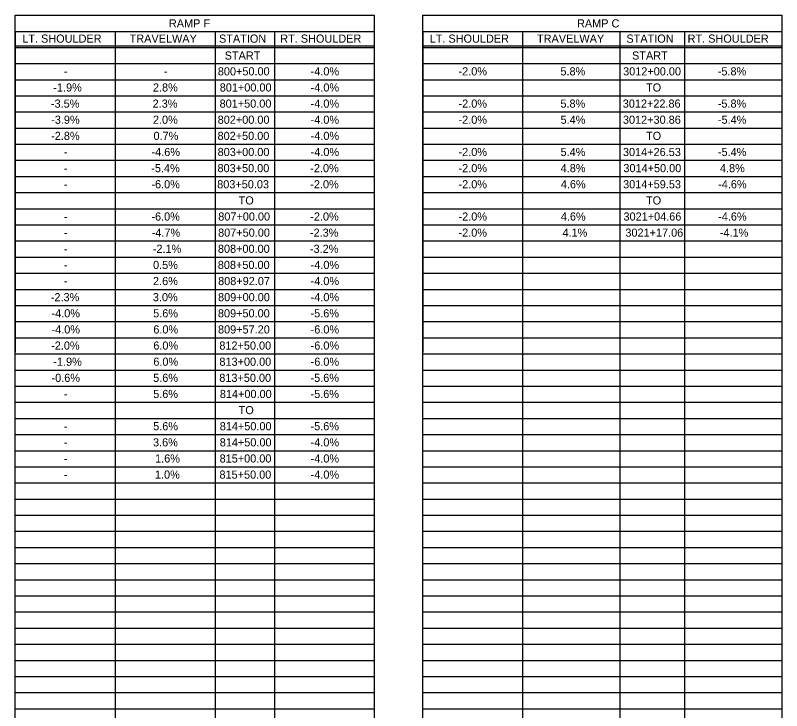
# Model space of a CAD drawing. Extents: x -15319374 to 1762012, y 465773 to 3693661.
# Drawn here: x -15316895.3 to -15316613.1, y 3692762.8 to 3693019 of the extents above; entities that cross this region are included whole.
import ezdxf

# ---------------------------------------------------------------- set-up
doc = ezdxf.new("R2010")
doc.units = 0
doc.layers.add('BORDER', color=7, linetype='Continuous')
doc.layers.add('DIMENSIONS', color=7, linetype='Continuous')

msp = doc.modelspace()

# ---------------------------------------------------------------- linework, layer by layer
at = {"layer": 'BORDER'}
for p, q in [((-15316895.32, 3693013.06), (-15316895.32, 3692894.86)), ((-15316858.55, 3693013.06), (-15316858.55, 3692507.99)), ((-15316821.78, 3693013.06), (-15316821.78, 3692507.99)), ((-15316799.91, 3693013.06), (-15316799.91, 3692507.99)), ((-15316745.32, 3693013.06), (-15316745.32, 3692894.86)), ((-15316708.55, 3693013.06), (-15316708.55, 3692507.99)), ((-15316672.78, 3693013.06), (-15316672.78, 3692507.99)), ((-15316648.91, 3693013.06), (-15316648.91, 3692507.99)), ((-15316895.32, 3693007.77), (-15316763.14, 3693007.77)), ((-15316745.32, 3693007.77), (-15316613.14, 3693007.77)), ((-15316895.32, 3693007.18), (-15316763.14, 3693007.18)), ((-15316745.32, 3693007.18), (-15316613.14, 3693007.18)), ((-15316895.32, 3693001.24), (-15316763.14, 3693001.24)), ((-15316895.32, 3693001.24), (-15316763.14, 3693001.24)), ((-15316895.32, 3693001.24), (-15316763.14, 3693001.24)), ((-15316745.32, 3693001.24), (-15316613.14, 3693001.24)), ((-15316745.32, 3693001.24), (-15316613.14, 3693001.24)), ((-15316745.32, 3693001.24), (-15316613.14, 3693001.24)), ((-15316895.32, 3692995.29), (-15316763.14, 3692995.29)), ((-15316745.32, 3692995.29), (-15316613.14, 3692995.29)), ((-15316895.32, 3692989.35), (-15316763.14, 3692989.35)), ((-15316745.32, 3692989.35), (-15316613.14, 3692989.35)), ((-15316895.32, 3692983.41), (-15316763.14, 3692983.41)), ((-15316745.32, 3692983.41), (-15316613.14, 3692983.41)), ((-15316895.32, 3692977.47), (-15316763.14, 3692977.47)), ((-15316745.32, 3692977.47), (-15316613.14, 3692977.47)), ((-15316895.32, 3692971.52), (-15316763.14, 3692971.52)), ((-15316745.32, 3692971.52), (-15316613.14, 3692971.52)), ((-15316895.32, 3692965.58), (-15316763.14, 3692965.58)), ((-15316745.32, 3692965.58), (-15316613.14, 3692965.58)), ((-15316895.32, 3692959.64), (-15316763.14, 3692959.64)), ((-15316745.32, 3692959.64), (-15316613.14, 3692959.64)), ((-15316895.32, 3692953.7), (-15316763.14, 3692953.7)), ((-15316745.32, 3692953.7), (-15316613.14, 3692953.7)), ((-15316895.32, 3692947.75), (-15316763.14, 3692947.75)), ((-15316745.32, 3692947.75), (-15316613.14, 3692947.75)), ((-15316895.32, 3692941.81), (-15316763.14, 3692941.81)), ((-15316745.32, 3692941.81), (-15316613.14, 3692941.81)), ((-15316895.32, 3692935.87), (-15316763.14, 3692935.87)), ((-15316745.32, 3692935.87), (-15316613.14, 3692935.87)), ((-15316895.32, 3692929.92), (-15316763.14, 3692929.92)), ((-15316745.32, 3692929.92), (-15316613.14, 3692929.92)), ((-15316895.32, 3692923.98), (-15316763.14, 3692923.98)), ((-15316745.32, 3692923.98), (-15316613.14, 3692923.98)), ((-15316895.32, 3692918.04), (-15316763.14, 3692918.04)), ((-15316745.32, 3692918.04), (-15316613.14, 3692918.04)), ((-15316895.32, 3692912.1), (-15316763.14, 3692912.1)), ((-15316745.32, 3692912.1), (-15316613.14, 3692912.1)), ((-15316895.32, 3692906.15), (-15316763.14, 3692906.15)), ((-15316745.32, 3692906.15), (-15316613.14, 3692906.15)), ((-15316895.32, 3692900.21), (-15316763.14, 3692900.21)), ((-15316745.32, 3692900.21), (-15316613.14, 3692900.21)), ((-15316895.32, 3692894.27), (-15316763.14, 3692894.27)), ((-15316745.32, 3692894.27), (-15316613.14, 3692894.27)), ((-15316895.32, 3692888.33), (-15316763.14, 3692888.33)), ((-15316745.32, 3692888.33), (-15316613.14, 3692888.33)), ((-15316895.32, 3692882.38), (-15316763.14, 3692882.38)), ((-15316745.32, 3692882.38), (-15316613.14, 3692882.38)), ((-15316895.32, 3692876.44), (-15316763.14, 3692876.44)), ((-15316745.32, 3692876.44), (-15316613.14, 3692876.44)), ((-15316895.32, 3692870.5), (-15316763.14, 3692870.5)), ((-15316745.32, 3692870.5), (-15316613.14, 3692870.5)), ((-15316895.32, 3692864.55), (-15316763.14, 3692864.55)), ((-15316745.32, 3692864.55), (-15316613.14, 3692864.55)), ((-15316895.32, 3692858.61), (-15316763.14, 3692858.61)), ((-15316745.32, 3692858.61), (-15316613.14, 3692858.61)), ((-15316895.32, 3692852.67), (-15316763.14, 3692852.67)), ((-15316745.32, 3692852.67), (-15316613.14, 3692852.67)), ((-15316895.32, 3692846.73), (-15316763.14, 3692846.73)), ((-15316745.32, 3692846.73), (-15316613.14, 3692846.73)), ((-15316895.32, 3692840.78), (-15316763.14, 3692840.78)), ((-15316745.32, 3692840.78), (-15316613.14, 3692840.78)), ((-15316895.32, 3692834.84), (-15316763.14, 3692834.84)), ((-15316745.32, 3692834.84), (-15316613.14, 3692834.84)), ((-15316895.32, 3692828.9), (-15316763.14, 3692828.9)), ((-15316745.32, 3692828.9), (-15316613.14, 3692828.9)), ((-15316895.32, 3692822.96), (-15316763.14, 3692822.96)), ((-15316745.32, 3692822.96), (-15316613.14, 3692822.96)), ((-15316895.32, 3692817.01), (-15316763.14, 3692817.01)), ((-15316745.32, 3692817.01), (-15316613.14, 3692817.01)), ((-15316895.32, 3692811.07), (-15316763.14, 3692811.07)), ((-15316745.32, 3692811.07), (-15316613.14, 3692811.07)), ((-15316895.32, 3692805.13), (-15316763.14, 3692805.13)), ((-15316745.32, 3692805.13), (-15316613.14, 3692805.13)), ((-15316895.32, 3692799.19), (-15316763.14, 3692799.19)), ((-15316745.32, 3692799.19), (-15316613.14, 3692799.19)), ((-15316895.32, 3692793.24), (-15316763.14, 3692793.24)), ((-15316745.32, 3692793.24), (-15316613.14, 3692793.24)), ((-15316895.32, 3692787.3), (-15316763.14, 3692787.3)), ((-15316745.32, 3692787.3), (-15316613.14, 3692787.3)), ((-15316895.32, 3692781.36), (-15316763.14, 3692781.36)), ((-15316745.32, 3692781.36), (-15316613.14, 3692781.36)), ((-15316895.32, 3692775.41), (-15316763.14, 3692775.41)), ((-15316745.32, 3692775.41), (-15316613.14, 3692775.41)), ((-15316895.32, 3692769.47), (-15316763.14, 3692769.47)), ((-15316745.32, 3692769.47), (-15316613.14, 3692769.47)), ((-15316895.32, 3692763.53), (-15316763.14, 3692763.53)), ((-15316745.32, 3692763.53), (-15316613.14, 3692763.53))]:
    msp.add_line(p, q, dxfattribs=at)
for points in [[(-15316895.32, 3693013.06), (-15316895.32, 3693019), (-15316763.14, 3693019), (-15316763.14, 3693013.06)], [(-15316745.32, 3693013.06), (-15316745.32, 3693019), (-15316613.14, 3693019), (-15316613.14, 3693013.06)]]:
    msp.add_lwpolyline(points, dxfattribs=at)
for points in [[(-15316895.32, 3693013.06), (-15316763.14, 3693013.06), (-15316763.14, 3692507.99), (-15316895.32, 3692507.99)], [(-15316745.32, 3693013.06), (-15316613.14, 3693013.06), (-15316613.14, 3692507.99), (-15316745.32, 3692507.99)]]:
    msp.add_lwpolyline(points, close=True, dxfattribs=at)

# ---------------------------------------------------------------- texts
at = {"layer": 'DIMENSIONS'}
for s, p in [('RAMP F', (-15316838.77, 3693014.53)), ('RAMP C', (-15316688.5, 3693014.53)), ('LT. SHOULDER', (-15316892.76, 3693008.92)), ('TRAVELWAY', (-15316853.23, 3693008.92)), ('STATION', (-15316820.32, 3693008.92)), ('RT. SHOULDER', (-15316797.78, 3693008.92)), ('LT. SHOULDER', (-15316742.76, 3693008.92)), ('TRAVELWAY', (-15316703.23, 3693008.92)), ('STATION', (-15316670.32, 3693008.92)), ('RT. SHOULDER', (-15316647.78, 3693008.92)), ('START', (-15316818.24, 3693002.69)), ('START', (-15316668.24, 3693002.69)), ('800+50.00', (-15316820.76, 3692996.86)), ('-4.0%', (-15316786.58, 3692996.86)), ('-2.0%', (-15316732.13, 3692996.86)), ('5.8%', (-15316694.61, 3692996.86)), ('3012+00.00', (-15316671.52, 3692996.86)), ('-5.8%', (-15316636.67, 3692996.86)), ('-', (-15316877.44, 3692996.86)), ('-', (-15316840.68, 3692996.86)), ('-1.9%', (-15316881.33, 3692990.92)), ('2.8%', (-15316844.65, 3692990.92)), ('801+00.00', (-15316820.05, 3692990.92)), ('-4.0%', (-15316786.58, 3692990.92)), ('TO', (-15316663.09, 3692990.92)), ('-3.5%', (-15316882.2, 3692984.98)), ('2.3%', (-15316844.77, 3692984.98)), ('801+50.00', (-15316820.1, 3692984.98)), ('-4.0%', (-15316786.58, 3692984.98)), ('-2.0%', (-15316732.13, 3692984.98)), ('5.8%', (-15316694.61, 3692984.98)), ('3012+22.86', (-15316671.66, 3692984.98)), ('-5.8%', (-15316636.67, 3692984.98)), ('-3.9%', (-15316882.11, 3692979.04)), ('2.0%', (-15316844.65, 3692979.04)), ('802+00.00', (-15316820.81, 3692979.04)), ('-4.0%', (-15316786.58, 3692979.04)), ('-2.0%', (-15316732.13, 3692979.04)), ('5.4%', (-15316694.56, 3692979.04)), ('3012+30.86', (-15316671.59, 3692979.04)), ('-5.4%', (-15316636.62, 3692979.04)), ('-2.8%', (-15316882.13, 3692973.09)), ('0.7%', (-15316844.44, 3692973.09)), ('802+50.00', (-15316820.86, 3692973.09)), ('-4.0%', (-15316786.58, 3692973.09)), ('TO', (-15316663.09, 3692973.09)), ('-', (-15316877.44, 3692967.15)), ('-4.6%', (-15316845.17, 3692967.15)), ('803+00.00', (-15316820.83, 3692967.15)), ('-4.0%', (-15316786.58, 3692967.15)), ('-2.0%', (-15316732.13, 3692967.15)), ('5.4%', (-15316694.56, 3692967.15)), ('3014+26.53', (-15316671.58, 3692967.15)), ('-5.4%', (-15316636.62, 3692967.15)), ('-5.4%', (-15316845.27, 3692961.21)), ('803+50.00', (-15316820.88, 3692961.21)), ('-2.0%', (-15316786.72, 3692961.21)), ('-2.0%', (-15316732.13, 3692961.21)), ('4.8%', (-15316694.51, 3692961.21)), ('3014+50.00', (-15316671.42, 3692961.21)), ('4.8%', (-15316635.87, 3692961.21)), ('-', (-15316877.44, 3692961.21)), ('-6.0%', (-15316845.22, 3692955.26)), ('803+50.03', (-15316820.99, 3692955.26)), ('-2.0%', (-15316786.72, 3692955.26)), ('-2.0%', (-15316732.13, 3692955.26)), ('4.6%', (-15316694.46, 3692955.26)), ('3014+59.53', (-15316671.53, 3692955.26)), ('-4.6%', (-15316636.53, 3692955.26)), ('-', (-15316877.44, 3692955.26)), ('TO', (-15316813.09, 3692949.32)), ('TO', (-15316663.09, 3692949.32)), ('-6.0%', (-15316845.22, 3692943.38)), ('807+00.00', (-15316820.6, 3692943.38)), ('-2.0%', (-15316786.72, 3692943.38)), ('-2.0%', (-15316732.13, 3692943.38)), ('4.6%', (-15316694.46, 3692943.38)), ('3021+04.66', (-15316671.38, 3692943.38)), ('-4.6%', (-15316636.53, 3692943.38)), ('-', (-15316877.44, 3692943.38)), ('-4.7%', (-15316845.1, 3692937.44)), ('807+50.00', (-15316820.65, 3692937.44)), ('-2.3%', (-15316786.84, 3692937.44)), ('-2.0%', (-15316732.13, 3692937.44)), ('4.1%', (-15316693.85, 3692937.44)), ('3021+17.06', (-15316670.69, 3692937.44)), ('-4.1%', (-15316635.91, 3692937.44)), ('-', (-15316877.44, 3692937.44)), ('-2.1%', (-15316844.7, 3692931.49)), ('808+00.00', (-15316820.72, 3692931.49)), ('-3.2%', (-15316786.84, 3692931.49)), ('-', (-15316877.44, 3692931.49)), ('-', (-15316877.44, 3692925.55)), ('0.5%', (-15316844.61, 3692925.55)), ('808+50.00', (-15316820.76, 3692925.55)), ('-4.0%', (-15316786.58, 3692925.55)), ('-', (-15316877.44, 3692919.61)), ('2.6%', (-15316844.61, 3692919.61)), ('808+92.07', (-15316820.64, 3692919.61)), ('-4.0%', (-15316786.58, 3692919.61)), ('-2.3%', (-15316882.25, 3692913.67)), ('3.0%', (-15316844.68, 3692913.67)), ('809+00.00', (-15316820.67, 3692913.67)), ('-4.0%', (-15316786.58, 3692913.67)), ('-4.0%', (-15316881.99, 3692907.72)), ('5.6%', (-15316844.56, 3692907.72)), ('809+50.00', (-15316820.72, 3692907.72)), ('-5.6%', (-15316786.62, 3692907.72)), ('-4.0%', (-15316881.99, 3692901.78)), ('6.0%', (-15316844.51, 3692901.78)), ('809+57.20', (-15316820.69, 3692901.78)), ('-6.0%', (-15316786.58, 3692901.78)), ('-2.0%', (-15316882.13, 3692895.84)), ('6.0%', (-15316844.51, 3692895.84)), ('812+50.00', (-15316820.2, 3692895.84)), ('-6.0%', (-15316786.58, 3692895.84)), ('-1.9%', (-15316881.33, 3692889.89)), ('6.0%', (-15316844.51, 3692889.89)), ('813+00.00', (-15316820.17, 3692889.89)), ('-6.0%', (-15316786.58, 3692889.89)), ('-0.6%', (-15316881.99, 3692883.95)), ('5.6%', (-15316844.56, 3692883.95)), ('813+50.00', (-15316820.22, 3692883.95)), ('-5.6%', (-15316786.62, 3692883.95)), ('5.6%', (-15316844.56, 3692878.01)), ('814+00.00', (-15316820.01, 3692878.01)), ('-5.6%', (-15316786.62, 3692878.01)), ('-', (-15316877.44, 3692878.01)), ('TO', (-15316813.09, 3692872.07)), ('-', (-15316877.44, 3692866.12)), ('5.6%', (-15316844.56, 3692866.12)), ('814+50.00', (-15316820.05, 3692866.12)), ('-5.6%', (-15316786.62, 3692866.12)), ('-', (-15316877.44, 3692860.18)), ('3.6%', (-15316844.63, 3692860.18)), ('814+50.00', (-15316820.05, 3692860.18)), ('-4.0%', (-15316786.58, 3692860.18)), ('-', (-15316877.44, 3692854.24)), ('1.6%', (-15316843.85, 3692854.24)), ('815+00.00', (-15316820.1, 3692854.24)), ('-4.0%', (-15316786.58, 3692854.24)), ('1.0%', (-15316843.9, 3692848.3)), ('815+50.00', (-15316820.15, 3692848.3)), ('-4.0%', (-15316786.58, 3692848.3)), ('-', (-15316877.44, 3692848.3))]:
    msp.add_text(s, height=3, dxfattribs=at).set_placement(p)

doc.saveas('drawing.dxf')
